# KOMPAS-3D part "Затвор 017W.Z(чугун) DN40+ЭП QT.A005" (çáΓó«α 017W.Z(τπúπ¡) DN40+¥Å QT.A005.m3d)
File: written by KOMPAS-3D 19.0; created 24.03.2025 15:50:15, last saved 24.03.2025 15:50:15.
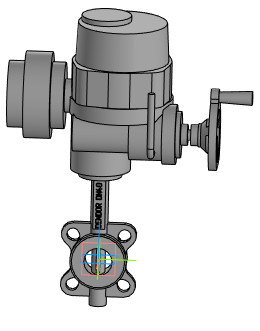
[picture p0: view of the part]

Document properties: Полное имя файла: Затвор 017W.Z(чугун) DN40+ЭП QT.A005.a3d

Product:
- Part/product: Затвор 017W.Z(чугун) DN40+ЭП QT.A005
    Масса: 38.0351

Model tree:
1. Операция без истории:1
